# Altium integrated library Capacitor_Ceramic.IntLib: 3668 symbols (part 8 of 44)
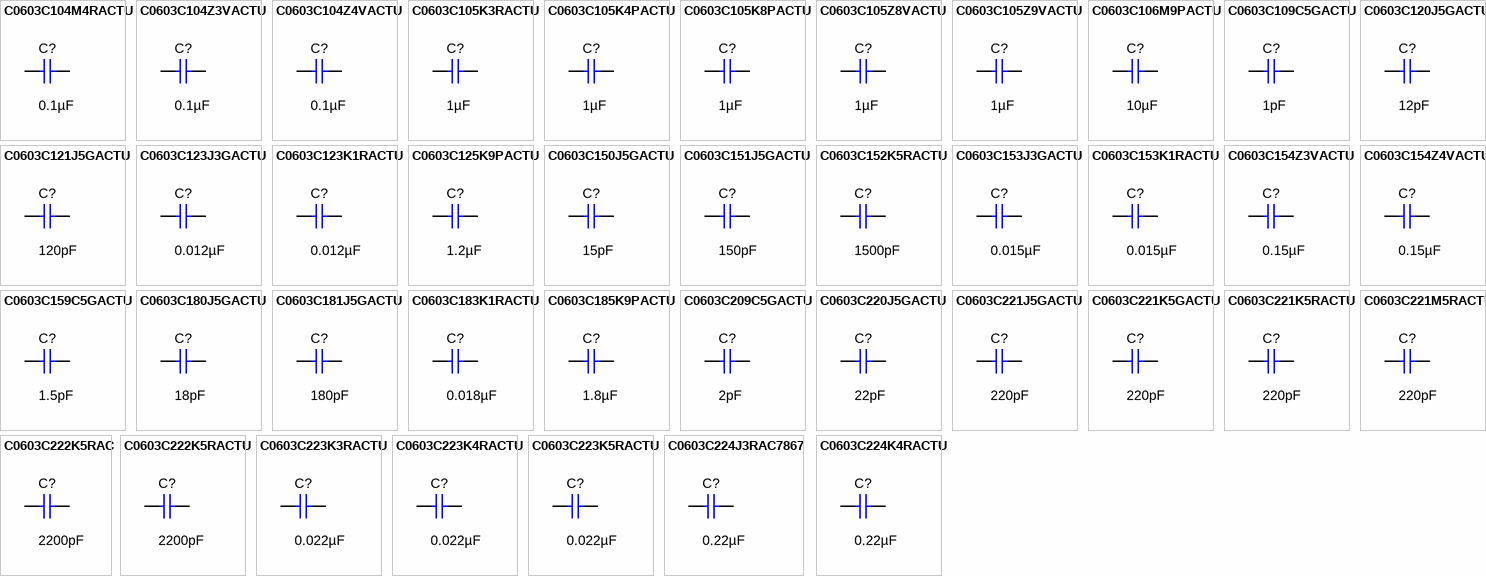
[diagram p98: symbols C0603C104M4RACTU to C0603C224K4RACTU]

## C0603C105K4PACTU
designator C?  ValueDisplayed: 1µF  (hidden comment: C0603C105K4PACTU)
CAP, CERM, 1 µF, 16 V,+/- 10%, X5R, 0603; Manufacturer: Kemet; Polarized: N; CompType: Capacitor; Value: 1uF; U/M: EA; Cap_F: 0.000001; Tolerance_%: 10; VDC_V: 16; Value2: 16V; TaMin_C: -55; TaMax_C: 85; Cap_Case: 0603; SizeArea_mm2: 1.28; SizeAreaWB_mm2: 4.68; SizeX_mm: 1.6; SizeY_mm: 0.8; SizeZ_mm: 1; AEC Category: Q200; Green_Lifecycle: Active; Green_REACh: Passed
signal-integrity model Cap
simulation model Cap
footprint 0603
footprint 0603M
footprint 0603L
footprint 0603_HV
footprint 0603S
pins: 1, 2

## C0603C105K8PACTU
designator C?  ValueDisplayed: 1µF  (hidden comment: C0603C105K8PACTU)
CAP, CERM, 1 µF, 10 V,+/- 10%, X5R, 0603; Manufacturer: Kemet; Polarized: N; CompType: Capacitor; Value: 1uF; U/M: EA; Cap_F: 0.000001; Tolerance_%: 10; Value2: 10V; TaMin_C: -55; TaMax_C: 85; Cap_Case: 0603; SizeArea_mm2: 1.28; SizeAreaWB_mm2: 4.68; SizeX_mm: 1.6; SizeY_mm: 0.8; SizeZ_mm: 1; AEC Category: Q200; Green_Lifecycle: Active; Green_REACh: Passed
signal-integrity model Cap
simulation model Cap
footprint 0603
footprint 0603M
footprint 0603L
footprint 0603_HV
footprint 0603S
pins: 1, 2

## C0603C105Z8VACTU
designator C?  ValueDisplayed: 1µF  (hidden comment: C0603C105Z8VACTU)
CAP, CERM, 1 µF, 10 V,+80/-20%, Y5V, 0603; Manufacturer: Kemet; Polarized: N; CompType: Capacitor; Value: 1uF; U/M: EA; Cap_F: 0.000001; Tolerance_%: 80; VDC_V: 10; Value2: 10V; TaMin_C: -30; TaMax_C: 85; Cap_Case: 0603; SizeArea_mm2: 1.28; SizeAreaWB_mm2: 4.68; SizeX_mm: 1.6; SizeY_mm: 0.8; SizeZ_mm: 1; AEC Category: Q200; Green_Lifecycle: Active; Green_REACh: Passed
signal-integrity model Cap
simulation model Cap
footprint 0603
footprint 0603M
footprint 0603L
footprint 0603_HV
footprint 0603S
pins: 1, 2

## C0603C105Z9VACTU
designator C?  ValueDisplayed: 1µF  (hidden comment: C0603C105Z9VACTU)
CAP, CERM, 1 µF, 6.3 V,+80/-20%, Y5V, 0603; Manufacturer: Kemet; Polarized: N; CompType: Capacitor; Value: 1uF; U/M: EA; Cap_F: 0.000001; Tolerance_%: 80; VDC_V: 6.3; Value2: 6.3V; TaMin_C: -30; TaMax_C: 85; Cap_Case: 0603; SizeArea_mm2: 1.28; SizeAreaWB_mm2: 4.68; SizeX_mm: 1.6; SizeY_mm: 0.8; SizeZ_mm: 1; AEC Category: Q200; Green_Lifecycle: Active; Green_REACh: Passed
signal-integrity model Cap
simulation model Cap
footprint 0603
footprint 0603M
footprint 0603L
footprint 0603_HV
footprint 0603S
pins: 1, 2

## C0603C106M9PACTU
designator C?  ValueDisplayed: 10µF  (hidden comment: C0603C106M9PACTU)
CAP, CERM, 10 µF, 6.3 V,+/- 20%, X5R, 0603; Manufacturer: Kemet; Polarized: N; CompType: Capacitor; Value: 10uF; U/M: EA; Cap_F: 0.00001; Tolerance_%: 20; ESR_ohm: 0.004; Value1: 0.004 ohm; VDC_V: 6.3; Value2: 6.3V; IRMS_A: 8.9; TaMin_C: -55; TaMax_C: 85; Cap_Case: 0603; SizeArea_mm2: 1.28; SizeAreaWB_mm2: 4.68; SizeX_mm: 1.6; SizeY_mm: 0.8; SizeZ_mm: 1; AEC Category: Q200; Green_Lifecycle: Active; Green_REACh: Passed
signal-integrity model Cap
simulation model Cap
footprint 0603
footprint 0603M
footprint 0603L
footprint 0603_HV
footprint 0603S
pins: 1, 2

## C0603C109C5GACTU
designator C?  ValueDisplayed: 1pF  (hidden comment: C0603C109C5GACTU)
CAP, CERM, 1 pF, 50 V,+/- 25%, C0G/NP0, 0603; Manufacturer: Kemet; Polarized: N; CompType: Capacitor; Value: 1pF; U/M: EA; Cap_F: 0.000000000001; Tolerance_%: 25; VDC_V: 50; Value2: 50V; TaMin_C: -55; TaMax_C: 125; Cap_Case: 0603; SizeArea_mm2: 1.28; SizeAreaWB_mm2: 4.68; SizeX_mm: 1.6; SizeY_mm: 0.8; SizeZ_mm: 1; AEC Category: Q200; Green_Lifecycle: Not Set; Green_REACh: Incomplete
signal-integrity model Cap
simulation model Cap
footprint 0603
footprint 0603M
footprint 0603L
footprint 0603_HV
footprint 0603S
pins: 1, 2

## C0603C120J5GACTU
designator C?  ValueDisplayed: 12pF  (hidden comment: C0603C120J5GACTU)
CAP, CERM, 12 pF, 50 V,+/- 5%, C0G/NP0, 0603; Manufacturer: Kemet; Polarized: N; CompType: Capacitor; Value: 12pF; U/M: EA; Cap_F: 0.000000000012; Tolerance_%: 5; VDC_V: 50; Value2: 50V; TaMin_C: -55; TaMax_C: 125; Cap_Case: 0603; SizeArea_mm2: 1.28; SizeAreaWB_mm2: 4.68; SizeX_mm: 1.6; SizeY_mm: 0.8; SizeZ_mm: 1; AEC Category: Q200; Green_Lifecycle: Active; Green_REACh: Passed
signal-integrity model Cap
simulation model Cap
footprint 0603
footprint 0603M
footprint 0603L
footprint 0603_HV
footprint 0603S
pins: 1, 2

## C0603C121J5GACTU
designator C?  ValueDisplayed: 120pF  (hidden comment: C0603C121J5GACTU)
CAP, CERM, 120 pF, 50 V,+/- 5%, C0G/NP0, 0603; Manufacturer: Kemet; Polarized: N; CompType: Capacitor; Value: 120pF; U/M: EA; Cap_F: 0.00000000012; Tolerance_%: 5; VDC_V: 50; Value2: 50V; TaMin_C: -55; TaMax_C: 125; Cap_Case: 0603; SizeArea_mm2: 1.28; SizeAreaWB_mm2: 4.68; SizeX_mm: 1.6; SizeY_mm: 0.8; SizeZ_mm: 1; AEC Category: Q200; Green_Lifecycle: Not Set; Green_REACh: Incomplete
signal-integrity model Cap
simulation model Cap
footprint 0603
footprint 0603M
footprint 0603L
footprint 0603_HV
footprint 0603S
pins: 1, 2

## C0603C123J3GACTU
designator C?  ValueDisplayed: 0.012µF  (hidden comment: C0603C123J3GACTU)
CAP, CERM, 0.012 µF, 25 V,+/- 5%, C0G/NP0, 0603; Manufacturer: Kemet; Polarized: N; CompType: Capacitor; Value: 0.012uF; U/M: EA; Cap_F: 0.000000012; Tolerance_%: 5; VDC_V: 25; Value2: 25V; TaMin_C: -55; TaMax_C: 125; Cap_Case: 0603; SizeArea_mm2: 1.28; SizeAreaWB_mm2: 4.68; SizeX_mm: 1.6; SizeY_mm: 0.8; SizeZ_mm: 1; AEC Category: Q200; Green_Lifecycle: Not Set; Green_REACh: Incomplete
signal-integrity model Cap
simulation model Cap
footprint 0603
footprint 0603M
footprint 0603L
footprint 0603_HV
footprint 0603S
pins: 1, 2

## C0603C123K1RACTU
designator C?  ValueDisplayed: 0.012µF  (hidden comment: C0603C123K1RACTU)
CAP, CERM, 0.012 µF, 100 V,+/- 10%, X7R, 0603; Manufacturer: Kemet; Polarized: N; CompType: Capacitor; Value: 0.012uF; U/M: EA; Cap_F: 0.000000012; Tolerance_%: 10; VDC_V: 100; Value2: 100V; TaMin_C: -55; TaMax_C: 125; Cap_Case: 0603; SizeArea_mm2: 1.28; SizeAreaWB_mm2: 4.68; SizeX_mm: 1.6; SizeY_mm: 0.8; SizeZ_mm: 1; AEC Category: Q200; Green_Lifecycle: Not Set; Green_REACh: Incomplete
signal-integrity model Cap
simulation model Cap
footprint 0603
footprint 0603M
footprint 0603L
footprint 0603_HV
footprint 0603S
pins: 1, 2

## C0603C125K9PACTU
designator C?  ValueDisplayed: 1.2µF  (hidden comment: C0603C125K9PACTU)
CAP, CERM, 1.2 µF, 6.3 V,+/- 10%, X5R, 0603; Manufacturer: Kemet; Polarized: N; CompType: Capacitor; Value: 1.2uF; U/M: EA; Cap_F: 0.0000012; Tolerance_%: 10; VDC_V: 6.3; Value2: 6.3V; TaMin_C: -55; TaMax_C: 85; Cap_Case: 0603; SizeArea_mm2: 1.28; SizeAreaWB_mm2: 4.68; SizeX_mm: 1.6; SizeY_mm: 0.8; SizeZ_mm: 1; AEC Category: Q200; Green_Lifecycle: Active; Green_REACh: Passed
signal-integrity model Cap
simulation model Cap
footprint 0603
footprint 0603M
footprint 0603L
footprint 0603_HV
footprint 0603S
pins: 1, 2

## C0603C150J5GACTU
designator C?  ValueDisplayed: 15pF  (hidden comment: C0603C150J5GACTU)
CAP, CERM, 15 pF, 50 V,+/- 5%, C0G/NP0, 0603; Manufacturer: Kemet; Polarized: N; CompType: Capacitor; Value: 15pF; U/M: EA; Cap_F: 0.000000000015; Tolerance_%: 5; VDC_V: 50; Value2: 50V; TaMin_C: -55; TaMax_C: 125; Cap_Case: 0603; SizeArea_mm2: 1.28; SizeAreaWB_mm2: 4.68; SizeX_mm: 1.6; SizeY_mm: 0.8; SizeZ_mm: 1; AEC Category: Q200; Green_Lifecycle: Active; Green_REACh: Passed
signal-integrity model Cap
simulation model Cap
footprint 0603
footprint 0603M
footprint 0603L
footprint 0603_HV
footprint 0603S
pins: 1, 2

## C0603C151J5GACTU
designator C?  ValueDisplayed: 150pF  (hidden comment: C0603C151J5GACTU)
CAP, CERM, 150 pF, 50 V,+/- 5%, C0G/NP0, 0603; Manufacturer: Kemet; Polarized: N; CompType: Capacitor; Value: 150pF; U/M: EA; Cap_F: 0.00000000015; Tolerance_%: 5; VDC_V: 50; Value2: 50V; TaMin_C: -55; TaMax_C: 125; Cap_Case: 0603; SizeArea_mm2: 1.28; SizeAreaWB_mm2: 4.68; SizeX_mm: 1.6; SizeY_mm: 0.8; SizeZ_mm: 1; AEC Category: Q200; Green_Lifecycle: Active; Green_REACh: Passed
signal-integrity model Cap
simulation model Cap
footprint 0603
footprint 0603M
footprint 0603L
footprint 0603_HV
footprint 0603S
pins: 1, 2

## C0603C152K5RACTU
designator C?  ValueDisplayed: 1500pF  (hidden comment: C0603C152K5RACTU)
CAP, CERM, 1500 pF, 50 V,+/- 10%, X7R, 0603; Manufacturer: Kemet; Polarized: N; CompType: Capacitor; Value: 1500pF; U/M: EA; Cap_F: 0.0000000015; Tolerance_%: 10; VDC_V: 50; Value2: 50V; TaMin_C: -55; TaMax_C: 125; Cap_Case: 0603; SizeArea_mm2: 1.28; SizeAreaWB_mm2: 4.68; SizeX_mm: 1.6; SizeY_mm: 0.8; SizeZ_mm: 1; AEC Category: Q200; Green_Lifecycle: Active; Green_REACh: Passed
signal-integrity model Cap
simulation model Cap
footprint 0603
footprint 0603M
footprint 0603L
footprint 0603_HV
footprint 0603S
pins: 1, 2

## C0603C153J3GACTU
designator C?  ValueDisplayed: 0.015µF  (hidden comment: C0603C153J3GACTU)
CAP, CERM, 0.015 µF, 25 V,+/- 5%, C0G/NP0, 0603; Manufacturer: Kemet; Polarized: N; CompType: Capacitor; Value: 0.015uF; U/M: EA; Cap_F: 0.000000015; Tolerance_%: 5; VDC_V: 25; Value2: 25V; TaMin_C: -55; TaMax_C: 125; Cap_Case: 0603; SizeArea_mm2: 1.28; SizeAreaWB_mm2: 4.68; SizeX_mm: 1.6; SizeY_mm: 0.8; SizeZ_mm: 1; AEC Category: Q200; Green_Lifecycle: Active; Green_REACh: Passed
signal-integrity model Cap
simulation model Cap
footprint 0603
footprint 0603M
footprint 0603L
footprint 0603_HV
footprint 0603S
pins: 1, 2

## C0603C153K1RACTU
designator C?  ValueDisplayed: 0.015µF  (hidden comment: C0603C153K1RACTU)
CAP, CERM, 0.015 µF, 100 V,+/- 10%, X7R, 0603; Manufacturer: Kemet; Polarized: N; CompType: Capacitor; Value: 0.015uF; U/M: EA; Cap_F: 0.000000015; Tolerance_%: 10; VDC_V: 100; Value2: 100V; TaMin_C: -55; TaMax_C: 125; Cap_Case: 0603; SizeArea_mm2: 1.28; SizeAreaWB_mm2: 4.68; SizeX_mm: 1.6; SizeY_mm: 0.8; SizeZ_mm: 1; AEC Category: Q200; Green_Lifecycle: Active; Green_REACh: Passed
signal-integrity model Cap
simulation model Cap
footprint 0603
footprint 0603M
footprint 0603L
footprint 0603_HV
footprint 0603S
pins: 1, 2

## C0603C154Z3VACTU
designator C?  ValueDisplayed: 0.15µF  (hidden comment: C0603C154Z3VACTU)
CAP, CERM, 0.15 µF, 25 V,+80/-20%, Y5V, 0603; Manufacturer: Kemet; Polarized: N; CompType: Capacitor; Value: 0.15uF; U/M: EA; Cap_F: 0.00000015; Tolerance_%: 80; VDC_V: 25; Value2: 25V; TaMin_C: -30; TaMax_C: 85; Cap_Case: 0603; SizeArea_mm2: 1.28; SizeAreaWB_mm2: 4.68; SizeX_mm: 1.6; SizeY_mm: 0.8; SizeZ_mm: 1; AEC Category: Q200; Green_Lifecycle: Not Set; Green_REACh: Incomplete
signal-integrity model Cap
simulation model Cap
footprint 0603
footprint 0603M
footprint 0603L
footprint 0603_HV
footprint 0603S
pins: 1, 2

## C0603C154Z4VACTU
designator C?  ValueDisplayed: 0.15µF  (hidden comment: C0603C154Z4VACTU)
CAP, CERM, 0.15 µF, 16 V,+80/-20%, Y5V, 0603; Manufacturer: Kemet; Polarized: N; CompType: Capacitor; Value: 0.15uF; U/M: EA; Cap_F: 0.00000015; Tolerance_%: 80; VDC_V: 16; Value2: 16V; TaMin_C: -30; TaMax_C: 85; Cap_Case: 0603; SizeArea_mm2: 1.28; SizeAreaWB_mm2: 4.68; SizeX_mm: 1.6; SizeY_mm: 0.8; SizeZ_mm: 1; AEC Category: Q200; Green_Lifecycle: Active; Green_REACh: Passed
signal-integrity model Cap
simulation model Cap
footprint 0603
footprint 0603M
footprint 0603L
footprint 0603_HV
footprint 0603S
pins: 1, 2

## C0603C159C5GACTU
designator C?  ValueDisplayed: 1.5pF  (hidden comment: C0603C159C5GACTU)
CAP, CERM, 1.5 pF, 50 V,+/- 16.7%, C0G/NP0, 0603; Manufacturer: Kemet; Polarized: N; CompType: Capacitor; Value: 1.5pF; U/M: EA; Cap_F: 0.0000000000015; Tolerance_%: 16.7; VDC_V: 50; Value2: 50V; TaMin_C: -55; TaMax_C: 125; Cap_Case: 0603; SizeArea_mm2: 1.28; SizeAreaWB_mm2: 4.68; SizeX_mm: 1.6; SizeY_mm: 0.8; SizeZ_mm: 1; AEC Category: Q200; Green_Lifecycle: Not Set; Green_REACh: Incomplete
signal-integrity model Cap
simulation model Cap
footprint 0603
footprint 0603M
footprint 0603L
footprint 0603_HV
footprint 0603S
pins: 1, 2

## C0603C180J5GACTU
designator C?  ValueDisplayed: 18pF  (hidden comment: C0603C180J5GACTU)
CAP, CERM, 18 pF, 50 V,+/- 5%, C0G/NP0, 0603; Manufacturer: Kemet; Polarized: N; CompType: Capacitor; Value: 18pF; U/M: EA; Cap_F: 0.000000000018; Tolerance_%: 5; VDC_V: 50; Value2: 50V; TaMin_C: -55; TaMax_C: 125; Cap_Case: 0603; SizeArea_mm2: 1.28; SizeAreaWB_mm2: 4.68; SizeX_mm: 1.6; SizeY_mm: 0.8; SizeZ_mm: 1; AEC Category: Q200; Green_Lifecycle: Not Set; Green_REACh: Incomplete
signal-integrity model Cap
simulation model Cap
footprint 0603
footprint 0603M
footprint 0603L
footprint 0603_HV
footprint 0603S
pins: 1, 2

## C0603C181J5GACTU
designator C?  ValueDisplayed: 180pF  (hidden comment: C0603C181J5GACTU)
CAP, CERM, 180 pF, 50 V,+/- 5%, C0G/NP0, 0603; Manufacturer: Kemet; Polarized: N; CompType: Capacitor; Value: 180pF; U/M: EA; Cap_F: 0.00000000018; Tolerance_%: 5; VDC_V: 50; Value2: 50V; TaMin_C: -55; TaMax_C: 125; Cap_Case: 0603; SizeArea_mm2: 1.28; SizeAreaWB_mm2: 4.68; SizeX_mm: 1.6; SizeY_mm: 0.8; SizeZ_mm: 1; AEC Category: Q200; Green_Lifecycle: Not Set; Green_REACh: Incomplete
signal-integrity model Cap
simulation model Cap
footprint 0603
footprint 0603M
footprint 0603L
footprint 0603_HV
footprint 0603S
pins: 1, 2

## C0603C183K1RACTU
designator C?  ValueDisplayed: 0.018µF  (hidden comment: C0603C183K1RACTU)
CAP, CERM, 0.018 µF, 100 V,+/- 10%, X7R, 0603; Manufacturer: Kemet; Polarized: N; CompType: Capacitor; Value: 0.018uF; U/M: EA; Cap_F: 0.000000018; Tolerance_%: 10; VDC_V: 100; Value2: 100V; TaMin_C: -55; TaMax_C: 125; Cap_Case: 0603; SizeArea_mm2: 1.28; SizeAreaWB_mm2: 4.68; SizeX_mm: 1.6; SizeY_mm: 0.8; SizeZ_mm: 1; AEC Category: Q200; Green_Lifecycle: Not Set; Green_REACh: Incomplete
signal-integrity model Cap
simulation model Cap
footprint 0603
footprint 0603M
footprint 0603L
footprint 0603_HV
footprint 0603S
pins: 1, 2

## C0603C185K9PACTU
designator C?  ValueDisplayed: 1.8µF  (hidden comment: C0603C185K9PACTU)
CAP, CERM, 1.8 µF, 6.3 V,+/- 10%, X5R, 0603; Manufacturer: Kemet; Polarized: N; CompType: Capacitor; Value: 1.8uF; U/M: EA; Cap_F: 0.0000018; Tolerance_%: 10; VDC_V: 6.3; Value2: 6.3V; TaMin_C: -55; TaMax_C: 85; Cap_Case: 0603; SizeArea_mm2: 1.28; SizeAreaWB_mm2: 4.68; SizeX_mm: 1.6; SizeY_mm: 0.8; SizeZ_mm: 1; AEC Category: Q200; Green_Lifecycle: Not Set; Green_REACh: Incomplete
signal-integrity model Cap
simulation model Cap
footprint 0603
footprint 0603M
footprint 0603L
footprint 0603_HV
footprint 0603S
pins: 1, 2

## C0603C209C5GACTU
designator C?  ValueDisplayed: 2pF  (hidden comment: C0603C209C5GACTU)
CAP, CERM, 2 pF, 50 V,+/- 12.5%, C0G/NP0, 0603; Manufacturer: Kemet; Polarized: N; CompType: Capacitor; Value: 2pF; U/M: EA; Cap_F: 0.000000000002; Tolerance_%: 12.5; VDC_V: 50; Value2: 50V; TaMin_C: -55; TaMax_C: 125; Cap_Case: 0603; SizeArea_mm2: 1.28; SizeAreaWB_mm2: 4.68; SizeX_mm: 1.6; SizeY_mm: 0.8; SizeZ_mm: 1; AEC Category: Q200; Green_Lifecycle: Active; Green_REACh: Passed
signal-integrity model Cap
simulation model Cap
footprint 0603
footprint 0603M
footprint 0603L
footprint 0603_HV
footprint 0603S
pins: 1, 2

## C0603C220J5GACTU
designator C?  ValueDisplayed: 22pF  (hidden comment: C0603C220J5GACTU)
CAP, CERM, 22 pF, 50 V,+/- 5%, C0G/NP0, 0603; Manufacturer: Kemet; Polarized: N; CompType: Capacitor; Value: 22pF; U/M: EA; Cap_F: 0.000000000022; Tolerance_%: 5; VDC_V: 50; Value2: 50V; TaMin_C: -55; TaMax_C: 125; Cap_Case: 0603; SizeArea_mm2: 1.28; SizeAreaWB_mm2: 4.68; SizeX_mm: 1.6; SizeY_mm: 0.8; SizeZ_mm: 1; AEC Category: Q200; Green_Lifecycle: Active; Green_REACh: Passed
signal-integrity model Cap
simulation model Cap
footprint 0603
footprint 0603M
footprint 0603L
footprint 0603_HV
footprint 0603S
pins: 1, 2

## C0603C221J5GACTU
designator C?  ValueDisplayed: 220pF  (hidden comment: C0603C221J5GACTU)
CAP, CERM, 220 pF, 50 V,+/- 5%, C0G/NP0, 0603; Manufacturer: Kemet; Polarized: N; CompType: Capacitor; Value: 220pF; U/M: EA; Cap_F: 0.00000000022; Tolerance_%: 5; VDC_V: 50; Value2: 50V; TaMin_C: -55; TaMax_C: 125; Cap_Case: 0603; SizeArea_mm2: 1.28; SizeAreaWB_mm2: 4.68; SizeX_mm: 1.6; SizeY_mm: 0.8; SizeZ_mm: 1; AEC Category: Q200; Green_Lifecycle: Active; Green_REACh: Passed
signal-integrity model Cap
simulation model Cap
footprint 0603
footprint 0603M
footprint 0603L
footprint 0603_HV
footprint 0603S
pins: 1, 2

## C0603C221K5GACTU
designator C?  ValueDisplayed: 220pF  (hidden comment: C0603C221K5GACTU)
CAP, CERM, 220 pF, 50 V,+/- 10%, C0G/NP0, 0603; Manufacturer: Kemet; Polarized: N; CompType: Capacitor; Value: 220pF; U/M: EA; Cap_F: 0.00000000022; Tolerance_%: 10; VDC_V: 50; Value2: 50V; TaMin_C: -55; TaMax_C: 125; Cap_Case: 0603; SizeArea_mm2: 1.28; SizeAreaWB_mm2: 4.68; SizeX_mm: 1.6; SizeY_mm: 0.8; SizeZ_mm: 1; AEC Category: Q200; Green_Lifecycle: Active; Green_REACh: Passed
signal-integrity model Cap
simulation model Cap
footprint 0603
footprint 0603M
footprint 0603L
footprint 0603_HV
footprint 0603S
pins: 1, 2

## C0603C221K5RACTU
designator C?  ValueDisplayed: 220pF  (hidden comment: C0603C221K5RACTU)
CAP, CERM, 220 pF, 50 V,+/- 10%, X7R, 0603; Manufacturer: Kemet; Polarized: N; CompType: Capacitor; Value: 220pF; U/M: EA; Cap_F: 0.00000000022; Tolerance_%: 10; VDC_V: 50; Value2: 50V; TaMin_C: -55; TaMax_C: 125; Cap_Case: 0603; SizeArea_mm2: 1.28; SizeAreaWB_mm2: 4.68; SizeX_mm: 1.6; SizeY_mm: 0.8; SizeZ_mm: 1; AEC Category: Q200; Green_Lifecycle: Active; Green_REACh: Passed
signal-integrity model Cap
simulation model Cap
footprint 0603
footprint 0603M
footprint 0603L
footprint 0603_HV
footprint 0603S
pins: 1, 2

## C0603C221M5RACTU
designator C?  ValueDisplayed: 220pF  (hidden comment: C0603C221M5RACTU)
CAP, CERM, 220 pF, 50 V,+/- 20%, X7R, 0603; Manufacturer: Kemet; Polarized: N; CompType: Capacitor; Value: 220pF; U/M: EA; Cap_F: 0.00000000022; Tolerance_%: 20; VDC_V: 50; Value2: 50V; TaMin_C: -55; TaMax_C: 125; Cap_Case: 0603; SizeArea_mm2: 1.28; SizeAreaWB_mm2: 4.68; SizeX_mm: 1.6; SizeY_mm: 0.8; SizeZ_mm: 1; AEC Category: Q200; Green_Lifecycle: Not Set; Green_REACh: Incomplete
signal-integrity model Cap
simulation model Cap
footprint 0603
footprint 0603M
footprint 0603L
footprint 0603_HV
footprint 0603S
pins: 1, 2

## C0603C222K5RAC
designator C?  ValueDisplayed: 2200pF  (hidden comment: C0603C222K5RAC)
CAP, CERM, 2200 pF, 50 V,+/- 10%, X7R, 0603; Manufacturer: Kemet; Polarized: N; CompType: Capacitor; Value: 2200pF; U/M: EA; Cap_F: 0.0000000022; Tolerance_%: 10; VDC_V: 50; Value2: 50V; TaMin_C: -55; TaMax_C: 125; Cap_Case: 0603; SizeArea_mm2: 1.28; SizeAreaWB_mm2: 4.68; SizeX_mm: 1.6; SizeY_mm: 0.8; SizeZ_mm: 1; AEC Category: Q200; Green_Lifecycle: Active; Green_REACh: Passed
signal-integrity model Cap
simulation model Cap
footprint 0603
footprint 0603M
footprint 0603L
footprint 0603_HV
footprint 0603S
pins: 1, 2

## C0603C222K5RACTU
designator C?  ValueDisplayed: 2200pF  (hidden comment: C0603C222K5RACTU)
CAP, CERM, 2200 pF, 50 V,+/- 10%, X7R, 0603; Manufacturer: Kemet; Polarized: N; CompType: Capacitor; Value: 2200pF; U/M: EA; Cap_F: 0.0000000022; Tolerance_%: 10; VDC_V: 50; Value2: 50V; TaMin_C: -55; TaMax_C: 125; Cap_Case: 0603; SizeArea_mm2: 1.28; SizeAreaWB_mm2: 4.68; SizeX_mm: 1.6; SizeY_mm: 0.8; SizeZ_mm: 1; AEC Category: Q200; Green_Lifecycle: Active; Green_REACh: Passed
signal-integrity model Cap
simulation model Cap
footprint 0603
footprint 0603M
footprint 0603L
footprint 0603_HV
footprint 0603S
pins: 1, 2

## C0603C223K3RACTU
designator C?  ValueDisplayed: 0.022µF  (hidden comment: C0603C223K3RACTU)
CAP, CERM, 0.022 µF, 25 V,+/- 10%, X7R, 0603; Manufacturer: Kemet; Polarized: N; CompType: Capacitor; Value: 0.022uF; U/M: EA; Cap_F: 0.000000022; Tolerance_%: 10; VDC_V: 25; Value2: 25V; TaMin_C: -55; TaMax_C: 125; Cap_Case: 0603; SizeArea_mm2: 1.28; SizeAreaWB_mm2: 4.68; SizeX_mm: 1.6; SizeY_mm: 0.8; SizeZ_mm: 1; AEC Category: Q200; Green_Lifecycle: Active; Green_REACh: Passed
signal-integrity model Cap
simulation model Cap
footprint 0603
footprint 0603M
footprint 0603L
footprint 0603_HV
footprint 0603S
pins: 1, 2

## C0603C223K4RACTU
designator C?  ValueDisplayed: 0.022µF  (hidden comment: C0603C223K4RACTU)
CAP, CERM, 0.022 µF, 16 V,+/- 10%, X7R, 0603; Manufacturer: Kemet; Polarized: N; CompType: Capacitor; Value: 0.022uF; U/M: EA; Cap_F: 0.000000022; Tolerance_%: 10; VDC_V: 16; Value2: 16V; TaMin_C: -55; TaMax_C: 125; Cap_Case: 0603; SizeArea_mm2: 1.28; SizeAreaWB_mm2: 4.68; SizeX_mm: 1.6; SizeY_mm: 0.8; SizeZ_mm: 1; AEC Category: Q200; Green_Lifecycle: Active; Green_REACh: Passed
signal-integrity model Cap
simulation model Cap
footprint 0603
footprint 0603M
footprint 0603L
footprint 0603_HV
footprint 0603S
pins: 1, 2

## C0603C223K5RACTU
designator C?  ValueDisplayed: 0.022µF  (hidden comment: C0603C223K5RACTU)
CAP, CERM, 0.022 µF, 50 V,+/- 10%, X7R, 0603; Manufacturer: Kemet; Polarized: N; CompType: Capacitor; Value: 0.022uF; U/M: EA; Cap_F: 0.000000022; Tolerance_%: 10; VDC_V: 50; Value2: 50V; TaMin_C: -55; TaMax_C: 125; Cap_Case: 0603; SizeArea_mm2: 1.28; SizeAreaWB_mm2: 4.68; SizeX_mm: 1.6; SizeY_mm: 0.8; SizeZ_mm: 1; AEC Category: Q200; Green_Lifecycle: Active; Green_REACh: Passed
signal-integrity model Cap
simulation model Cap
footprint 0603
footprint 0603M
footprint 0603L
footprint 0603_HV
footprint 0603S
pins: 1, 2

## C0603C224J3RAC7867
designator C?  ValueDisplayed: 0.22µF  (hidden comment: C0603C224J3RAC7867)
CAP, CERM, 0.22 µF, 25 V,+/- 5%, X7R, 0603; Manufacturer: Kemet; Polarized: N; CompType: Capacitor; Value: 0.22uF; U/M: EA; Cap_F: 0.00000022; Tolerance_%: 5; VDC_V: 25; Value2: 25V; TaMin_C: -55; TaMax_C: 125; Cap_Case: 0603; SizeArea_mm2: 1.28; SizeAreaWB_mm2: 4.68; SizeX_mm: 1.6; SizeY_mm: 0.8; SizeZ_mm: 1; AEC Category: Q200; Green_Lifecycle: Active; Green_REACh: Passed
signal-integrity model Cap
simulation model Cap
footprint 0603
footprint 0603M
footprint 0603L
footprint 0603_HV
footprint 0603S
pins: 1, 2

## C0603C224K4RACTU
designator C?  ValueDisplayed: 0.22µF  (hidden comment: C0603C224K4RACTU)
CAP, CERM, 0.22 µF, 16 V,+/- 10%, X7R, 0603; Manufacturer: Kemet; Polarized: N; CompType: Capacitor; Value: 0.22uF; U/M: EA; Cap_F: 0.00000022; Tolerance_%: 10; VDC_V: 16; Value2: 16V; TaMin_C: -55; TaMax_C: 125; Cap_Case: 0603; SizeArea_mm2: 1.28; SizeAreaWB_mm2: 4.68; SizeX_mm: 1.6; SizeY_mm: 0.8; SizeZ_mm: 1; AEC Category: Q200; Green_Lifecycle: Active; Green_REACh: Passed
signal-integrity model Cap
simulation model Cap
footprint 0603
footprint 0603M
footprint 0603L
footprint 0603_HV
footprint 0603S
pins: 1, 2

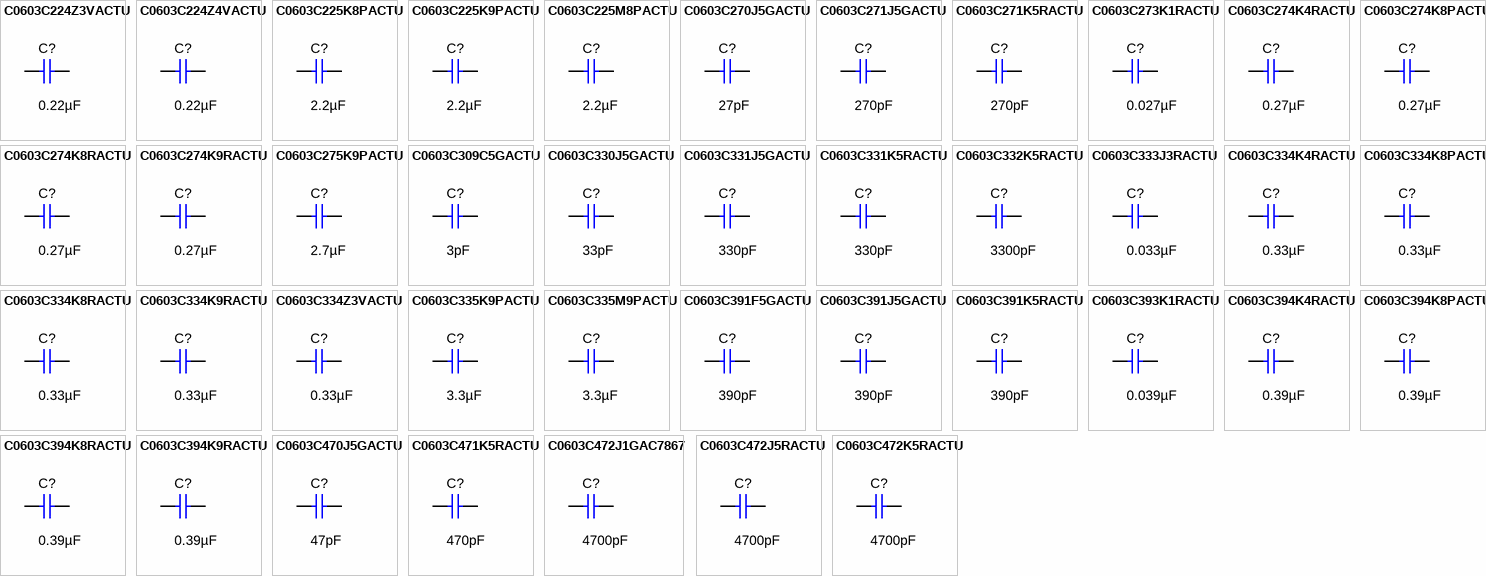
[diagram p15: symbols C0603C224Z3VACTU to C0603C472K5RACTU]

## C0603C224Z3VACTU
designator C?  ValueDisplayed: 0.22µF  (hidden comment: C0603C224Z3VACTU)
CAP, CERM, 0.22 µF, 25 V,+80/-20%, Y5V, 0603; Manufacturer: Kemet; Polarized: N; CompType: Capacitor; Value: 0.22uF; U/M: EA; Cap_F: 0.00000022; Tolerance_%: 80; VDC_V: 25; Value2: 25V; TaMin_C: -30; TaMax_C: 85; Cap_Case: 0603; SizeArea_mm2: 1.28; SizeAreaWB_mm2: 4.68; SizeX_mm: 1.6; SizeY_mm: 0.8; SizeZ_mm: 1; AEC Category: Q200; Green_Lifecycle: Not Set; Green_REACh: Incomplete
signal-integrity model Cap
simulation model Cap
footprint 0603
footprint 0603M
footprint 0603L
footprint 0603_HV
footprint 0603S
pins: 1, 2

## C0603C224Z4VACTU
designator C?  ValueDisplayed: 0.22µF  (hidden comment: C0603C224Z4VACTU)
CAP, CERM, 0.22 µF, 16 V,+80/-20%, Y5V, 0603; Manufacturer: Kemet; Polarized: N; CompType: Capacitor; Value: 0.22uF; U/M: EA; Cap_F: 0.00000022; Tolerance_%: 80; VDC_V: 16; Value2: 16V; TaMin_C: -30; TaMax_C: 85; Cap_Case: 0603; SizeArea_mm2: 1.28; SizeAreaWB_mm2: 4.68; SizeX_mm: 1.6; SizeY_mm: 0.8; SizeZ_mm: 1; AEC Category: Q200; Green_Lifecycle: Active; Green_REACh: Passed
signal-integrity model Cap
simulation model Cap
footprint 0603
footprint 0603M
footprint 0603L
footprint 0603_HV
footprint 0603S
pins: 1, 2

## C0603C225K8PACTU
designator C?  ValueDisplayed: 2.2µF  (hidden comment: C0603C225K8PACTU)
CAP, CERM, 2.2 µF, 10 V,+/- 10%, X5R, 0603; Manufacturer: Kemet; Polarized: N; CompType: Capacitor; Value: 2.2uF; U/M: EA; Cap_F: 0.0000022; Tolerance_%: 10; Value2: 10V; TaMin_C: -55; TaMax_C: 85; Cap_Case: 0603; SizeArea_mm2: 1.28; SizeAreaWB_mm2: 4.68; SizeX_mm: 1.6; SizeY_mm: 0.8; SizeZ_mm: 1; AEC Category: Q200; Green_Lifecycle: Active; Green_REACh: Passed
signal-integrity model Cap
simulation model Cap
footprint 0603
footprint 0603M
footprint 0603L
footprint 0603_HV
footprint 0603S
pins: 1, 2

## C0603C225K9PACTU
designator C?  ValueDisplayed: 2.2µF  (hidden comment: C0603C225K9PACTU)
CAP, CERM, 2.2 µF, 6.3 V,+/- 10%, X5R, 0603; Manufacturer: Kemet; Polarized: N; CompType: Capacitor; Value: 2.2uF; U/M: EA; Cap_F: 0.0000022; Tolerance_%: 10; VDC_V: 6.3; Value2: 6.3V; TaMin_C: -55; TaMax_C: 85; Cap_Case: 0603; SizeArea_mm2: 1.28; SizeAreaWB_mm2: 4.68; SizeX_mm: 1.6; SizeY_mm: 0.8; SizeZ_mm: 1; AEC Category: Q200; Green_Lifecycle: Active; Green_REACh: Passed
signal-integrity model Cap
simulation model Cap
footprint 0603
footprint 0603M
footprint 0603L
footprint 0603_HV
footprint 0603S
pins: 1, 2

## C0603C225M8PACTU
designator C?  ValueDisplayed: 2.2µF  (hidden comment: C0603C225M8PACTU)
CAP, CERM, 2.2 µF, 10 V,+/- 20%, X5R, 0603; Manufacturer: Kemet; Polarized: N; CompType: Capacitor; Value: 2.2uF; U/M: EA; Cap_F: 0.0000022; Tolerance_%: 20; VDC_V: 10; Value2: 10V; TaMin_C: -55; TaMax_C: 85; Cap_Case: 0603; SizeArea_mm2: 1.28; SizeAreaWB_mm2: 4.68; SizeX_mm: 1.6; SizeY_mm: 0.8; SizeZ_mm: 1; AEC Category: Q200; Green_Lifecycle: Active; Green_REACh: Passed
signal-integrity model Cap
simulation model Cap
footprint 0603
footprint 0603M
footprint 0603L
footprint 0603_HV
footprint 0603S
pins: 1, 2

## C0603C270J5GACTU
designator C?  ValueDisplayed: 27pF  (hidden comment: C0603C270J5GACTU)
CAP, CERM, 27 pF, 50 V,+/- 5%, C0G/NP0, 0603; Manufacturer: Kemet; Polarized: N; CompType: Capacitor; Value: 27pF; U/M: EA; Cap_F: 0.000000000027; Tolerance_%: 5; VDC_V: 50; Value2: 50V; TaMin_C: -55; TaMax_C: 125; Cap_Case: 0603; SizeArea_mm2: 1.28; SizeAreaWB_mm2: 4.68; SizeX_mm: 1.6; SizeY_mm: 0.8; SizeZ_mm: 1; AEC Category: Q200; Green_Lifecycle: Not Set; Green_REACh: Incomplete
signal-integrity model Cap
simulation model Cap
footprint 0603
footprint 0603M
footprint 0603L
footprint 0603_HV
footprint 0603S
pins: 1, 2

## C0603C271J5GACTU
designator C?  ValueDisplayed: 270pF  (hidden comment: C0603C271J5GACTU)
CAP, CERM, 270 pF, 50 V,+/- 5%, C0G/NP0, 0603; Manufacturer: Kemet; Polarized: N; CompType: Capacitor; Value: 270pF; U/M: EA; Cap_F: 0.00000000027; Tolerance_%: 5; VDC_V: 50; Value2: 50V; TaMin_C: -55; TaMax_C: 125; Cap_Case: 0603; SizeArea_mm2: 1.28; SizeAreaWB_mm2: 4.68; SizeX_mm: 1.6; SizeY_mm: 0.8; SizeZ_mm: 1; AEC Category: Q200; Green_Lifecycle: Active; Green_REACh: Passed
signal-integrity model Cap
simulation model Cap
footprint 0603
footprint 0603M
footprint 0603L
footprint 0603_HV
footprint 0603S
pins: 1, 2

## C0603C271K5RACTU
designator C?  ValueDisplayed: 270pF  (hidden comment: C0603C271K5RACTU)
CAP, CERM, 270 pF, 50 V,+/- 10%, X7R, 0603; Manufacturer: Kemet; Polarized: N; CompType: Capacitor; Value: 270pF; U/M: EA; Cap_F: 0.00000000027; Tolerance_%: 10; VDC_V: 50; Value2: 50V; TaMin_C: -55; TaMax_C: 125; Cap_Case: 0603; SizeArea_mm2: 1.28; SizeAreaWB_mm2: 4.68; SizeX_mm: 1.6; SizeY_mm: 0.8; SizeZ_mm: 1; AEC Category: Q200; Green_Lifecycle: Not Set; Green_REACh: Incomplete
signal-integrity model Cap
simulation model Cap
footprint 0603
footprint 0603M
footprint 0603L
footprint 0603_HV
footprint 0603S
pins: 1, 2

## C0603C273K1RACTU
designator C?  ValueDisplayed: 0.027µF  (hidden comment: C0603C273K1RACTU)
CAP, CERM, 0.027 µF, 100 V,+/- 10%, X7R, 0603; Manufacturer: Kemet; Polarized: N; CompType: Capacitor; Value: 0.027uF; U/M: EA; Cap_F: 0.000000027; Tolerance_%: 10; VDC_V: 100; Value2: 100V; TaMin_C: -55; TaMax_C: 125; Cap_Case: 0603; SizeArea_mm2: 1.28; SizeAreaWB_mm2: 4.68; SizeX_mm: 1.6; SizeY_mm: 0.8; SizeZ_mm: 1; AEC Category: Q200; Green_Lifecycle: Not Set; Green_REACh: Incomplete
signal-integrity model Cap
simulation model Cap
footprint 0603
footprint 0603M
footprint 0603L
footprint 0603_HV
footprint 0603S
pins: 1, 2

## C0603C274K4RACTU
designator C?  ValueDisplayed: 0.27µF  (hidden comment: C0603C274K4RACTU)
CAP, CERM, 0.27 µF, 16 V,+/- 10%, X7R, 0603; Manufacturer: Kemet; Polarized: N; CompType: Capacitor; Value: 0.27uF; U/M: EA; Cap_F: 0.00000027; Tolerance_%: 10; VDC_V: 16; Value2: 16V; TaMin_C: -55; TaMax_C: 125; Cap_Case: 0603; SizeArea_mm2: 1.28; SizeAreaWB_mm2: 4.68; SizeX_mm: 1.6; SizeY_mm: 0.8; SizeZ_mm: 1; AEC Category: Q200; Green_Lifecycle: Not Set; Green_REACh: Incomplete
signal-integrity model Cap
simulation model Cap
footprint 0603
footprint 0603M
footprint 0603L
footprint 0603_HV
footprint 0603S
pins: 1, 2

## C0603C274K8PACTU
designator C?  ValueDisplayed: 0.27µF  (hidden comment: C0603C274K8PACTU)
CAP, CERM, 0.27 µF, 10 V,+/- 10%, X5R, 0603; Manufacturer: Kemet; Polarized: N; CompType: Capacitor; Value: 0.27uF; U/M: EA; Cap_F: 0.00000027; Tolerance_%: 10; Value2: 10V; TaMin_C: -55; TaMax_C: 85; Cap_Case: 0603; SizeArea_mm2: 1.28; SizeAreaWB_mm2: 4.68; SizeX_mm: 1.6; SizeY_mm: 0.8; SizeZ_mm: 1; AEC Category: Q200; Green_Lifecycle: Active; Green_REACh: Passed
signal-integrity model Cap
simulation model Cap
footprint 0603
footprint 0603M
footprint 0603L
footprint 0603_HV
footprint 0603S
pins: 1, 2

## C0603C274K8RACTU
designator C?  ValueDisplayed: 0.27µF  (hidden comment: C0603C274K8RACTU)
CAP, CERM, 0.27 µF, 10 V,+/- 10%, X7R, 0603; Manufacturer: Kemet; Polarized: N; CompType: Capacitor; Value: 0.27uF; U/M: EA; Cap_F: 0.00000027; Tolerance_%: 10; Value2: 10V; TaMin_C: -55; TaMax_C: 125; Cap_Case: 0603; SizeArea_mm2: 1.28; SizeAreaWB_mm2: 4.68; SizeX_mm: 1.6; SizeY_mm: 0.8; SizeZ_mm: 1; AEC Category: Q200; Green_Lifecycle: Not Set; Green_REACh: Incomplete
signal-integrity model Cap
simulation model Cap
footprint 0603
footprint 0603M
footprint 0603L
footprint 0603_HV
footprint 0603S
pins: 1, 2

## C0603C274K9RACTU
designator C?  ValueDisplayed: 0.27µF  (hidden comment: C0603C274K9RACTU)
CAP, CERM, 0.27 µF, 6.3 V,+/- 10%, X7R, 0603; Manufacturer: Kemet; Polarized: N; CompType: Capacitor; Value: 0.27uF; U/M: EA; Cap_F: 0.00000027; Tolerance_%: 10; VDC_V: 6.3; Value2: 6.3V; TaMin_C: -55; TaMax_C: 125; Cap_Case: 0603; SizeArea_mm2: 1.28; SizeAreaWB_mm2: 4.68; SizeX_mm: 1.6; SizeY_mm: 0.8; SizeZ_mm: 1; AEC Category: Q200; Green_Lifecycle: Not Set; Green_REACh: Incomplete
signal-integrity model Cap
simulation model Cap
footprint 0603
footprint 0603M
footprint 0603L
footprint 0603_HV
footprint 0603S
pins: 1, 2

## C0603C275K9PACTU
designator C?  ValueDisplayed: 2.7µF  (hidden comment: C0603C275K9PACTU)
CAP, CERM, 2.7 µF, 6.3 V,+/- 10%, X5R, 0603; Manufacturer: Kemet; Polarized: N; CompType: Capacitor; Value: 2.7uF; U/M: EA; Cap_F: 0.0000027; Tolerance_%: 10; VDC_V: 6.3; Value2: 6.3V; TaMin_C: -55; TaMax_C: 85; Cap_Case: 0603; SizeArea_mm2: 1.28; SizeAreaWB_mm2: 4.68; SizeX_mm: 1.6; SizeY_mm: 0.8; SizeZ_mm: 1; AEC Category: Q200; Green_Lifecycle: Not Set; Green_REACh: Incomplete
signal-integrity model Cap
simulation model Cap
footprint 0603
footprint 0603M
footprint 0603L
footprint 0603_HV
footprint 0603S
pins: 1, 2

## C0603C309C5GACTU
designator C?  ValueDisplayed: 3pF  (hidden comment: C0603C309C5GACTU)
CAP, CERM, 3 pF, 50 V,+/- 8.3%, C0G/NP0, 0603; Manufacturer: Kemet; Polarized: N; CompType: Capacitor; Value: 3pF; U/M: EA; Cap_F: 0.000000000003; Tolerance_%: 8.3; VDC_V: 50; Value2: 50V; TaMin_C: -55; TaMax_C: 125; Cap_Case: 0603; SizeArea_mm2: 1.28; SizeAreaWB_mm2: 4.68; SizeX_mm: 1.6; SizeY_mm: 0.8; SizeZ_mm: 1; AEC Category: Q200; Green_Lifecycle: Not Set; Green_REACh: Incomplete
signal-integrity model Cap
simulation model Cap
footprint 0603
footprint 0603M
footprint 0603L
footprint 0603_HV
footprint 0603S
pins: 1, 2

## C0603C330J5GACTU
designator C?  ValueDisplayed: 33pF  (hidden comment: C0603C330J5GACTU)
CAP, CERM, 33 pF, 50 V,+/- 5%, C0G/NP0, 0603; Manufacturer: Kemet; Polarized: N; CompType: Capacitor; Value: 33pF; U/M: EA; Cap_F: 0.000000000033; Tolerance_%: 5; VDC_V: 50; Value2: 50V; TaMin_C: -55; TaMax_C: 125; Cap_Case: 0603; SizeArea_mm2: 1.28; SizeAreaWB_mm2: 4.68; SizeX_mm: 1.6; SizeY_mm: 0.8; SizeZ_mm: 1; AEC Category: Q200; Green_Lifecycle: Active; Green_REACh: Passed
signal-integrity model Cap
simulation model Cap
footprint 0603
footprint 0603M
footprint 0603L
footprint 0603_HV
footprint 0603S
pins: 1, 2

## C0603C331J5GACTU
designator C?  ValueDisplayed: 330pF  (hidden comment: C0603C331J5GACTU)
CAP, CERM, 330 pF, 50 V,+/- 5%, C0G/NP0, 0603; Manufacturer: Kemet; Polarized: N; CompType: Capacitor; Value: 330pF; U/M: EA; Cap_F: 0.00000000033; Tolerance_%: 5; VDC_V: 50; Value2: 50V; TaMin_C: -55; TaMax_C: 125; Cap_Case: 0603; SizeArea_mm2: 1.28; SizeAreaWB_mm2: 4.68; SizeX_mm: 1.6; SizeY_mm: 0.8; SizeZ_mm: 1; AEC Category: Q200; Green_Lifecycle: Active; Green_REACh: Passed
signal-integrity model Cap
simulation model Cap
footprint 0603
footprint 0603M
footprint 0603L
footprint 0603_HV
footprint 0603S
pins: 1, 2

## C0603C331K5RACTU
designator C?  ValueDisplayed: 330pF  (hidden comment: C0603C331K5RACTU)
CAP, CERM, 330 pF, 50 V,+/- 10%, X7R, 0603; Manufacturer: Kemet; Polarized: N; CompType: Capacitor; Value: 330pF; U/M: EA; Cap_F: 0.00000000033; Tolerance_%: 10; VDC_V: 50; Value2: 50V; TaMin_C: -55; TaMax_C: 125; Cap_Case: 0603; SizeArea_mm2: 1.28; SizeAreaWB_mm2: 4.68; SizeX_mm: 1.6; SizeY_mm: 0.8; SizeZ_mm: 1; AEC Category: Q200; Green_Lifecycle: Active; Green_REACh: Passed
signal-integrity model Cap
simulation model Cap
footprint 0603
footprint 0603M
footprint 0603L
footprint 0603_HV
footprint 0603S
pins: 1, 2

## C0603C332K5RACTU
designator C?  ValueDisplayed: 3300pF  (hidden comment: C0603C332K5RACTU)
CAP, CERM, 3300 pF, 50 V,+/- 10%, X7R, 0603; Manufacturer: Kemet; Polarized: N; CompType: Capacitor; Value: 3300pF; U/M: EA; Cap_F: 0.0000000033; Tolerance_%: 10; VDC_V: 50; Value2: 50V; TaMin_C: -55; TaMax_C: 125; Cap_Case: 0603; SizeArea_mm2: 1.28; SizeAreaWB_mm2: 4.68; SizeX_mm: 1.6; SizeY_mm: 0.8; SizeZ_mm: 1; AEC Category: Q200; Green_Lifecycle: Active; Green_REACh: Passed
signal-integrity model Cap
simulation model Cap
footprint 0603
footprint 0603M
footprint 0603L
footprint 0603_HV
footprint 0603S
pins: 1, 2

## C0603C333J3RACTU
designator C?  ValueDisplayed: 0.033µF  (hidden comment: C0603C333J3RACTU)
CAP, CERM, 0.033 µF, 25 V,+/- 5%, X7R, 0603; Manufacturer: Kemet; Polarized: N; CompType: Capacitor; Value: 0.033uF; U/M: EA; Cap_F: 0.000000033; Tolerance_%: 5; VDC_V: 25; Value2: 25V; TaMin_C: -55; TaMax_C: 125; Cap_Case: 0603; SizeArea_mm2: 1.28; SizeAreaWB_mm2: 4.68; SizeX_mm: 1.6; SizeY_mm: 0.8; SizeZ_mm: 1; AEC Category: Q200
signal-integrity model Cap
simulation model Cap
footprint 0603
footprint 0603M
footprint 0603L
footprint 0603_HV
footprint 0603S
pins: 1, 2

## C0603C334K4RACTU
designator C?  ValueDisplayed: 0.33µF  (hidden comment: C0603C334K4RACTU)
CAP, CERM, 0.33 µF, 16 V,+/- 10%, X7R, 0603; Manufacturer: Kemet; Polarized: N; CompType: Capacitor; Value: 0.33uF; U/M: EA; Cap_F: 0.00000033; Tolerance_%: 10; VDC_V: 16; Value2: 16V; TaMin_C: -55; TaMax_C: 125; Cap_Case: 0603; SizeArea_mm2: 1.28; SizeAreaWB_mm2: 4.68; SizeX_mm: 1.6; SizeY_mm: 0.8; SizeZ_mm: 1; AEC Category: Q200; Green_Lifecycle: Active; Green_REACh: Passed
signal-integrity model Cap
simulation model Cap
footprint 0603
footprint 0603M
footprint 0603L
footprint 0603_HV
footprint 0603S
pins: 1, 2

## C0603C334K8PACTU
designator C?  ValueDisplayed: 0.33µF  (hidden comment: C0603C334K8PACTU)
CAP, CERM, 0.33 µF, 10 V,+/- 10%, X5R, 0603; Manufacturer: Kemet; Polarized: N; CompType: Capacitor; Value: 0.33uF; U/M: EA; Cap_F: 0.00000033; Tolerance_%: 10; Value2: 10V; TaMin_C: -55; TaMax_C: 85; Cap_Case: 0603; SizeArea_mm2: 1.28; SizeAreaWB_mm2: 4.68; SizeX_mm: 1.6; SizeY_mm: 0.8; SizeZ_mm: 1; AEC Category: Q200; Green_Lifecycle: Not Set; Green_REACh: Incomplete
signal-integrity model Cap
simulation model Cap
footprint 0603
footprint 0603M
footprint 0603L
footprint 0603_HV
footprint 0603S
pins: 1, 2

## C0603C334K8RACTU
designator C?  ValueDisplayed: 0.33µF  (hidden comment: C0603C334K8RACTU)
CAP, CERM, 0.33 µF, 10 V,+/- 10%, X7R, 0603; Manufacturer: Kemet; Polarized: N; CompType: Capacitor; Value: 0.33uF; U/M: EA; Cap_F: 0.00000033; Tolerance_%: 10; Value2: 10V; TaMin_C: -55; TaMax_C: 125; Cap_Case: 0603; SizeArea_mm2: 1.28; SizeAreaWB_mm2: 4.68; SizeX_mm: 1.6; SizeY_mm: 0.8; SizeZ_mm: 1; AEC Category: Q200; Green_Lifecycle: Not Set; Green_REACh: Incomplete
signal-integrity model Cap
simulation model Cap
footprint 0603
footprint 0603M
footprint 0603L
footprint 0603_HV
footprint 0603S
pins: 1, 2

## C0603C334K9RACTU
designator C?  ValueDisplayed: 0.33µF  (hidden comment: C0603C334K9RACTU)
CAP, CERM, 0.33 µF, 6.3 V,+/- 10%, X7R, 0603; Manufacturer: Kemet; Polarized: N; CompType: Capacitor; Value: 0.33uF; U/M: EA; Cap_F: 0.00000033; Tolerance_%: 10; VDC_V: 6.3; Value2: 6.3V; TaMin_C: -55; TaMax_C: 125; Cap_Case: 0603; SizeArea_mm2: 1.28; SizeAreaWB_mm2: 4.68; SizeX_mm: 1.6; SizeY_mm: 0.8; SizeZ_mm: 1; AEC Category: Q200; Green_Lifecycle: Not Set; Green_REACh: Incomplete
signal-integrity model Cap
simulation model Cap
footprint 0603
footprint 0603M
footprint 0603L
footprint 0603_HV
footprint 0603S
pins: 1, 2

## C0603C334Z3VACTU
designator C?  ValueDisplayed: 0.33µF  (hidden comment: C0603C334Z3VACTU)
CAP, CERM, 0.33 µF, 25 V,+80/-20%, Y5V, 0603; Manufacturer: Kemet; Polarized: N; CompType: Capacitor; Value: 0.33uF; U/M: EA; Cap_F: 0.00000033; Tolerance_%: 80; VDC_V: 25; Value2: 25V; TaMin_C: -30; TaMax_C: 85; Cap_Case: 0603; SizeArea_mm2: 1.28; SizeAreaWB_mm2: 4.68; SizeX_mm: 1.6; SizeY_mm: 0.8; SizeZ_mm: 1; AEC Category: Q200; Green_Lifecycle: Active; Green_REACh: Passed
signal-integrity model Cap
simulation model Cap
footprint 0603
footprint 0603M
footprint 0603L
footprint 0603_HV
footprint 0603S
pins: 1, 2

## C0603C335K9PACTU
designator C?  ValueDisplayed: 3.3µF  (hidden comment: C0603C335K9PACTU)
CAP, CERM, 3.3 µF, 6.3 V,+/- 10%, X5R, 0603; Manufacturer: Kemet; Polarized: N; CompType: Capacitor; Value: 3.3uF; U/M: EA; Cap_F: 0.0000033; Tolerance_%: 10; ESR_ohm: 0.009; Value1: 0.009 ohm; VDC_V: 6.3; Value2: 6.3V; IRMS_A: 6.13; TaMin_C: -55; TaMax_C: 85; Cap_Case: 0603; SizeArea_mm2: 1.28; SizeAreaWB_mm2: 4.68; SizeX_mm: 1.6; SizeY_mm: 0.8; SizeZ_mm: 1; AEC Category: Q200; Green_Lifecycle: Not Set; Green_REACh: Incomplete
signal-integrity model Cap
simulation model Cap
footprint 0603
footprint 0603M
footprint 0603L
footprint 0603_HV
footprint 0603S
pins: 1, 2

## C0603C335M9PACTU
designator C?  ValueDisplayed: 3.3µF  (hidden comment: C0603C335M9PACTU)
CAP, CERM, 3.3 µF, 6.3 V,+/- 20%, X5R, 0603; Manufacturer: Kemet; Polarized: N; CompType: Capacitor; Value: 3.3uF; U/M: EA; Cap_F: 0.0000033; Tolerance_%: 20; ESR_ohm: 0.009; Value1: 0.009 ohm; VDC_V: 6.3; Value2: 6.3V; IRMS_A: 6.13; TaMin_C: -55; TaMax_C: 85; Cap_Case: 0603; SizeArea_mm2: 1.28; SizeAreaWB_mm2: 4.68; SizeX_mm: 1.6; SizeY_mm: 0.8; SizeZ_mm: 1; AEC Category: Q200; Green_Lifecycle: Not Set; Green_REACh: Incomplete
signal-integrity model Cap
simulation model Cap
footprint 0603
footprint 0603M
footprint 0603L
footprint 0603_HV
footprint 0603S
pins: 1, 2

## C0603C391F5GACTU
designator C?  ValueDisplayed: 390pF  (hidden comment: C0603C391F5GACTU)
CAP, CERM, 390 pF, 50 V,+/- 1%, C0G/NP0, 0603; Manufacturer: Kemet; Polarized: N; CompType: Capacitor; Value: 390pF; U/M: EA; Cap_F: 0.00000000039; Tolerance_%: 1; VDC_V: 50; Value2: 50V; TaMin_C: -55; TaMax_C: 125; Cap_Case: 0603; SizeArea_mm2: 1.28; SizeAreaWB_mm2: 4.68; SizeX_mm: 1.6; SizeY_mm: 0.8; AEC Category: Q200; Green_Lifecycle: Not Set; Green_REACh: Incomplete
signal-integrity model Cap
simulation model Cap
footprint 0603
footprint 0603M
footprint 0603L
footprint 0603_HV
footprint 0603S
pins: 1, 2

## C0603C391J5GACTU
designator C?  ValueDisplayed: 390pF  (hidden comment: C0603C391J5GACTU)
CAP, CERM, 390 pF, 50 V,+/- 5%, C0G/NP0, 0603; Manufacturer: Kemet; Polarized: N; CompType: Capacitor; Value: 390pF; U/M: EA; Cap_F: 0.00000000039; Tolerance_%: 5; VDC_V: 50; Value2: 50V; TaMin_C: -55; TaMax_C: 125; Cap_Case: 0603; SizeArea_mm2: 1.28; SizeAreaWB_mm2: 4.68; SizeX_mm: 1.6; SizeY_mm: 0.8; SizeZ_mm: 1; AEC Category: Q200; Green_Lifecycle: Not Set; Green_REACh: Incomplete
signal-integrity model Cap
simulation model Cap
footprint 0603
footprint 0603M
footprint 0603L
footprint 0603_HV
footprint 0603S
pins: 1, 2

## C0603C391K5RACTU
designator C?  ValueDisplayed: 390pF  (hidden comment: C0603C391K5RACTU)
CAP, CERM, 390 pF, 50 V,+/- 10%, X7R, 0603; Manufacturer: Kemet; Polarized: N; CompType: Capacitor; Value: 390pF; U/M: EA; Cap_F: 0.00000000039; Tolerance_%: 10; VDC_V: 50; Value2: 50V; TaMin_C: -55; TaMax_C: 125; Cap_Case: 0603; SizeArea_mm2: 1.28; SizeAreaWB_mm2: 4.68; SizeX_mm: 1.6; SizeY_mm: 0.8; SizeZ_mm: 1; AEC Category: Q200; Green_Lifecycle: Not Set; Green_REACh: Incomplete
signal-integrity model Cap
simulation model Cap
footprint 0603
footprint 0603M
footprint 0603L
footprint 0603_HV
footprint 0603S
pins: 1, 2

## C0603C393K1RACTU
designator C?  ValueDisplayed: 0.039µF  (hidden comment: C0603C393K1RACTU)
CAP, CERM, 0.039 µF, 100 V,+/- 10%, X7R, 0603; Manufacturer: Kemet; Polarized: N; CompType: Capacitor; Value: 0.039uF; U/M: EA; Cap_F: 0.000000039; Tolerance_%: 10; VDC_V: 100; Value2: 100V; TaMin_C: -55; TaMax_C: 125; Cap_Case: 0603; SizeArea_mm2: 1.28; SizeAreaWB_mm2: 4.68; SizeX_mm: 1.6; SizeY_mm: 0.8; SizeZ_mm: 1; AEC Category: Q200; Green_Lifecycle: Not Set; Green_REACh: Incomplete
signal-integrity model Cap
simulation model Cap
footprint 0603
footprint 0603M
footprint 0603L
footprint 0603_HV
footprint 0603S
pins: 1, 2

## C0603C394K4RACTU
designator C?  ValueDisplayed: 0.39µF  (hidden comment: C0603C394K4RACTU)
CAP, CERM, 0.39 µF, 16 V,+/- 10%, X7R, 0603; Manufacturer: Kemet; Polarized: N; CompType: Capacitor; Value: 0.39uF; U/M: EA; Cap_F: 0.00000039; Tolerance_%: 10; VDC_V: 16; Value2: 16V; TaMin_C: -55; TaMax_C: 125; Cap_Case: 0603; SizeArea_mm2: 1.28; SizeAreaWB_mm2: 4.68; SizeX_mm: 1.6; SizeY_mm: 0.8; SizeZ_mm: 1; AEC Category: Q200; Green_Lifecycle: Active; Green_REACh: Passed
signal-integrity model Cap
simulation model Cap
footprint 0603
footprint 0603M
footprint 0603L
footprint 0603_HV
footprint 0603S
pins: 1, 2

## C0603C394K8PACTU
designator C?  ValueDisplayed: 0.39µF  (hidden comment: C0603C394K8PACTU)
CAP, CERM, 0.39 µF, 10 V,+/- 10%, X5R, 0603; Manufacturer: Kemet; Polarized: N; CompType: Capacitor; Value: 0.39uF; U/M: EA; Cap_F: 0.00000039; Tolerance_%: 10; Value2: 10V; TaMin_C: -55; TaMax_C: 85; Cap_Case: 0603; SizeArea_mm2: 1.28; SizeAreaWB_mm2: 4.68; SizeX_mm: 1.6; SizeY_mm: 0.8; SizeZ_mm: 1; AEC Category: Q200; Green_Lifecycle: Active; Green_REACh: Passed
signal-integrity model Cap
simulation model Cap
footprint 0603
footprint 0603M
footprint 0603L
footprint 0603_HV
footprint 0603S
pins: 1, 2

## C0603C394K8RACTU
designator C?  ValueDisplayed: 0.39µF  (hidden comment: C0603C394K8RACTU)
CAP, CERM, 0.39 µF, 10 V,+/- 10%, X7R, 0603; Manufacturer: Kemet; Polarized: N; CompType: Capacitor; Value: 0.39uF; U/M: EA; Cap_F: 0.00000039; Tolerance_%: 10; Value2: 10V; TaMin_C: -55; TaMax_C: 125; Cap_Case: 0603; SizeArea_mm2: 1.28; SizeAreaWB_mm2: 4.68; SizeX_mm: 1.6; SizeY_mm: 0.8; SizeZ_mm: 1; AEC Category: Q200; Green_Lifecycle: Not Set; Green_REACh: Incomplete
signal-integrity model Cap
simulation model Cap
footprint 0603
footprint 0603M
footprint 0603L
footprint 0603_HV
footprint 0603S
pins: 1, 2

## C0603C394K9RACTU
designator C?  ValueDisplayed: 0.39µF  (hidden comment: C0603C394K9RACTU)
CAP, CERM, 0.39 µF, 6.3 V,+/- 10%, X7R, 0603; Manufacturer: Kemet; Polarized: N; CompType: Capacitor; Value: 0.39uF; U/M: EA; Cap_F: 0.00000039; Tolerance_%: 10; VDC_V: 6.3; Value2: 6.3V; TaMin_C: -55; TaMax_C: 125; Cap_Case: 0603; SizeArea_mm2: 1.28; SizeAreaWB_mm2: 4.68; SizeX_mm: 1.6; SizeY_mm: 0.8; SizeZ_mm: 1; AEC Category: Q200; Green_Lifecycle: Not Set; Green_REACh: Incomplete
signal-integrity model Cap
simulation model Cap
footprint 0603
footprint 0603M
footprint 0603L
footprint 0603_HV
footprint 0603S
pins: 1, 2

## C0603C470J5GACTU
designator C?  ValueDisplayed: 47pF  (hidden comment: C0603C470J5GACTU)
CAP, CERM, 47 pF, 50 V,+/- 5%, C0G/NP0, 0603; Manufacturer: Kemet; Polarized: N; CompType: Capacitor; Value: 47pF; U/M: EA; Cap_F: 0.000000000047; Tolerance_%: 5; VDC_V: 50; Value2: 50V; TaMin_C: -55; TaMax_C: 125; Cap_Case: 0603; SizeArea_mm2: 1.28; SizeAreaWB_mm2: 4.68; SizeX_mm: 1.6; SizeY_mm: 0.8; SizeZ_mm: 1; AEC Category: Q200; Green_Lifecycle: Active; Green_REACh: Passed
signal-integrity model Cap
simulation model Cap
footprint 0603
footprint 0603M
footprint 0603L
footprint 0603_HV
footprint 0603S
pins: 1, 2

## C0603C471K5RACTU
designator C?  ValueDisplayed: 470pF  (hidden comment: C0603C471K5RACTU)
CAP, CERM, 470 pF, 50 V,+/- 10%, X7R, 0603; Manufacturer: Kemet; Polarized: N; CompType: Capacitor; Value: 470pF; U/M: EA; Cap_F: 0.00000000047; Tolerance_%: 10; VDC_V: 50; Value2: 50V; TaMin_C: -55; TaMax_C: 125; Cap_Case: 0603; SizeArea_mm2: 1.28; SizeAreaWB_mm2: 4.68; SizeX_mm: 1.6; SizeY_mm: 0.8; SizeZ_mm: 1; AEC Category: Q200; Green_Lifecycle: Active; Green_REACh: Passed
signal-integrity model Cap
simulation model Cap
footprint 0603
footprint 0603M
footprint 0603L
footprint 0603_HV
footprint 0603S
pins: 1, 2

## C0603C472J1GAC7867
designator C?  ValueDisplayed: 4700pF  (hidden comment: C0603C472J1GAC7867)
CAP, CERM, 4700 pF, 100 V,+/- 5%, C0G/NP0, 0603; Manufacturer: Kemet; Polarized: N; CompType: Capacitor; Value: 4700pF; U/M: EA; Cap_F: 0.0000000047; Tolerance_%: 5; VDC_V: 100; Value2: 100V; TaMin_C: -55; TaMax_C: 125; Cap_Case: 0603; SizeArea_mm2: 1.28; SizeAreaWB_mm2: 4.68; SizeX_mm: 1.6; SizeY_mm: 0.8; SizeZ_mm: 1; AEC Category: Q200; Green_Lifecycle: Not Set; Green_REACh: Incomplete
signal-integrity model Cap
simulation model Cap
footprint 0603
footprint 0603M
footprint 0603L
footprint 0603_HV
footprint 0603S
pins: 1, 2

## C0603C472J5RACTU
designator C?  ValueDisplayed: 4700pF  (hidden comment: C0603C472J5RACTU)
CAP, CERM, 4700 pF, 50 V,+/- 5%, X7R, 0603; Manufacturer: Kemet; Polarized: N; CompType: Capacitor; Value: 4700pF; U/M: EA; Cap_F: 0.0000000047; Tolerance_%: 5; VDC_V: 50; Value2: 50V; TaMin_C: -55; TaMax_C: 125; Cap_Case: 0603; SizeArea_mm2: 1.28; SizeAreaWB_mm2: 4.68; SizeX_mm: 1.6; SizeY_mm: 0.8; SizeZ_mm: 1; AEC Category: Q200; Green_Lifecycle: Active; Green_REACh: Passed
signal-integrity model Cap
simulation model Cap
footprint 0603
footprint 0603M
footprint 0603L
footprint 0603_HV
footprint 0603S
pins: 1, 2

## C0603C472K5RACTU
designator C?  ValueDisplayed: 4700pF  (hidden comment: C0603C472K5RACTU)
CAP, CERM, 4700 pF, 50 V,+/- 10%, X7R, 0603; Manufacturer: Kemet; Polarized: N; CompType: Capacitor; Value: 4700pF; U/M: EA; Cap_F: 0.0000000047; Tolerance_%: 10; VDC_V: 50; Value2: 50V; TaMin_C: -55; TaMax_C: 125; Cap_Case: 0603; SizeArea_mm2: 1.28; SizeAreaWB_mm2: 4.68; SizeX_mm: 1.6; SizeY_mm: 0.8; SizeZ_mm: 1; AEC Category: Q200; Green_Lifecycle: Active; Green_REACh: Passed
signal-integrity model Cap
simulation model Cap
footprint 0603
footprint 0603M
footprint 0603L
footprint 0603_HV
footprint 0603S
pins: 1, 2

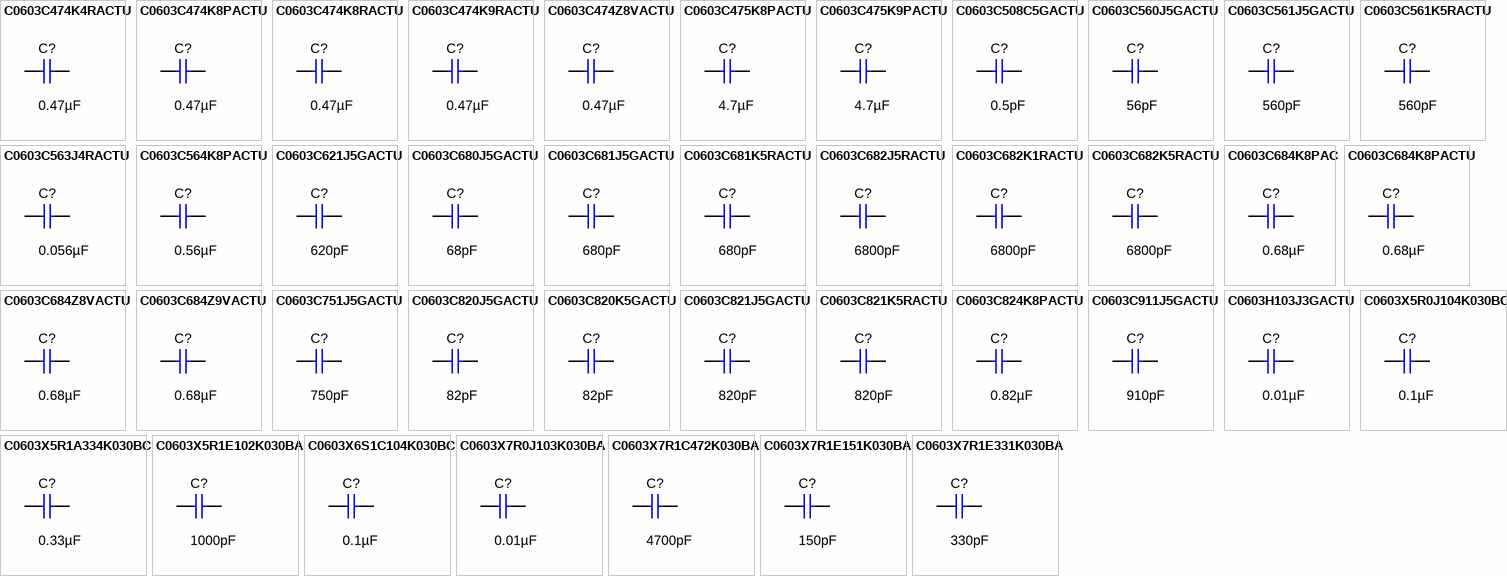
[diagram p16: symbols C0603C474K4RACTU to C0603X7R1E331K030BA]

## C0603C474K4RACTU
designator C?  ValueDisplayed: 0.47µF  (hidden comment: C0603C474K4RACTU)
CAP, CERM, 0.47 µF, 16 V,+/- 10%, X7R, 0603; Manufacturer: Kemet; Polarized: N; CompType: Capacitor; Value: 0.47uF; U/M: EA; Cap_F: 0.00000047; Tolerance_%: 10; VDC_V: 16; Value2: 16V; TaMin_C: -55; TaMax_C: 125; Cap_Case: 0603; SizeArea_mm2: 1.28; SizeAreaWB_mm2: 4.68; SizeX_mm: 1.6; SizeY_mm: 0.8; SizeZ_mm: 1; AEC Category: Q200; Green_Lifecycle: Active; Green_REACh: Passed
signal-integrity model Cap
simulation model Cap
footprint 0603
footprint 0603M
footprint 0603L
footprint 0603_HV
footprint 0603S
pins: 1, 2

## C0603C474K8PACTU
designator C?  ValueDisplayed: 0.47µF  (hidden comment: C0603C474K8PACTU)
CAP, CERM, 0.47 µF, 10 V,+/- 10%, X5R, 0603; Manufacturer: Kemet; Polarized: N; CompType: Capacitor; Value: 0.47uF; U/M: EA; Cap_F: 0.00000047; Tolerance_%: 10; Value2: 10V; TaMin_C: -55; TaMax_C: 85; Cap_Case: 0603; SizeArea_mm2: 1.28; SizeAreaWB_mm2: 4.68; SizeX_mm: 1.6; SizeY_mm: 0.8; SizeZ_mm: 1; AEC Category: Q200; Green_Lifecycle: Active; Green_REACh: Passed
signal-integrity model Cap
simulation model Cap
footprint 0603
footprint 0603M
footprint 0603L
footprint 0603_HV
footprint 0603S
pins: 1, 2

## C0603C474K8RACTU
designator C?  ValueDisplayed: 0.47µF  (hidden comment: C0603C474K8RACTU)
CAP, CERM, 0.47 µF, 10 V,+/- 10%, X7R, 0603; Manufacturer: Kemet; Polarized: N; CompType: Capacitor; Value: 0.47uF; U/M: EA; Cap_F: 0.00000047; Tolerance_%: 10; Value2: 10V; TaMin_C: -55; TaMax_C: 125; Cap_Case: 0603; SizeArea_mm2: 1.28; SizeAreaWB_mm2: 4.68; SizeX_mm: 1.6; SizeY_mm: 0.8; SizeZ_mm: 1; AEC Category: Q200; Green_Lifecycle: Active; Green_REACh: Passed
signal-integrity model Cap
simulation model Cap
footprint 0603
footprint 0603M
footprint 0603L
footprint 0603_HV
footprint 0603S
pins: 1, 2

## C0603C474K9RACTU
designator C?  ValueDisplayed: 0.47µF  (hidden comment: C0603C474K9RACTU)
CAP, CERM, 0.47 µF, 6.3 V,+/- 10%, X7R, 0603; Manufacturer: Kemet; Polarized: N; CompType: Capacitor; Value: 0.47uF; U/M: EA; Cap_F: 0.00000047; Tolerance_%: 10; VDC_V: 6.3; Value2: 6.3V; TaMin_C: -55; TaMax_C: 125; Cap_Case: 0603; SizeArea_mm2: 1.28; SizeAreaWB_mm2: 4.68; SizeX_mm: 1.6; SizeY_mm: 0.8; SizeZ_mm: 1; AEC Category: Q200; Green_Lifecycle: Active; Green_REACh: Passed
signal-integrity model Cap
simulation model Cap
footprint 0603
footprint 0603M
footprint 0603L
footprint 0603_HV
footprint 0603S
pins: 1, 2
